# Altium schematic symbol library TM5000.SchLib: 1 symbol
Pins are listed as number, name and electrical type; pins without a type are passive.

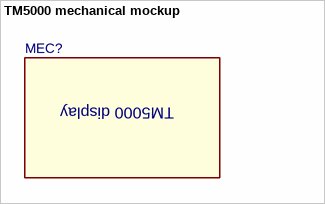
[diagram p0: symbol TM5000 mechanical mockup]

## TM5000 mechanical mockup
designator MEC?  (value not drawn)
footprint PCBComponent_1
